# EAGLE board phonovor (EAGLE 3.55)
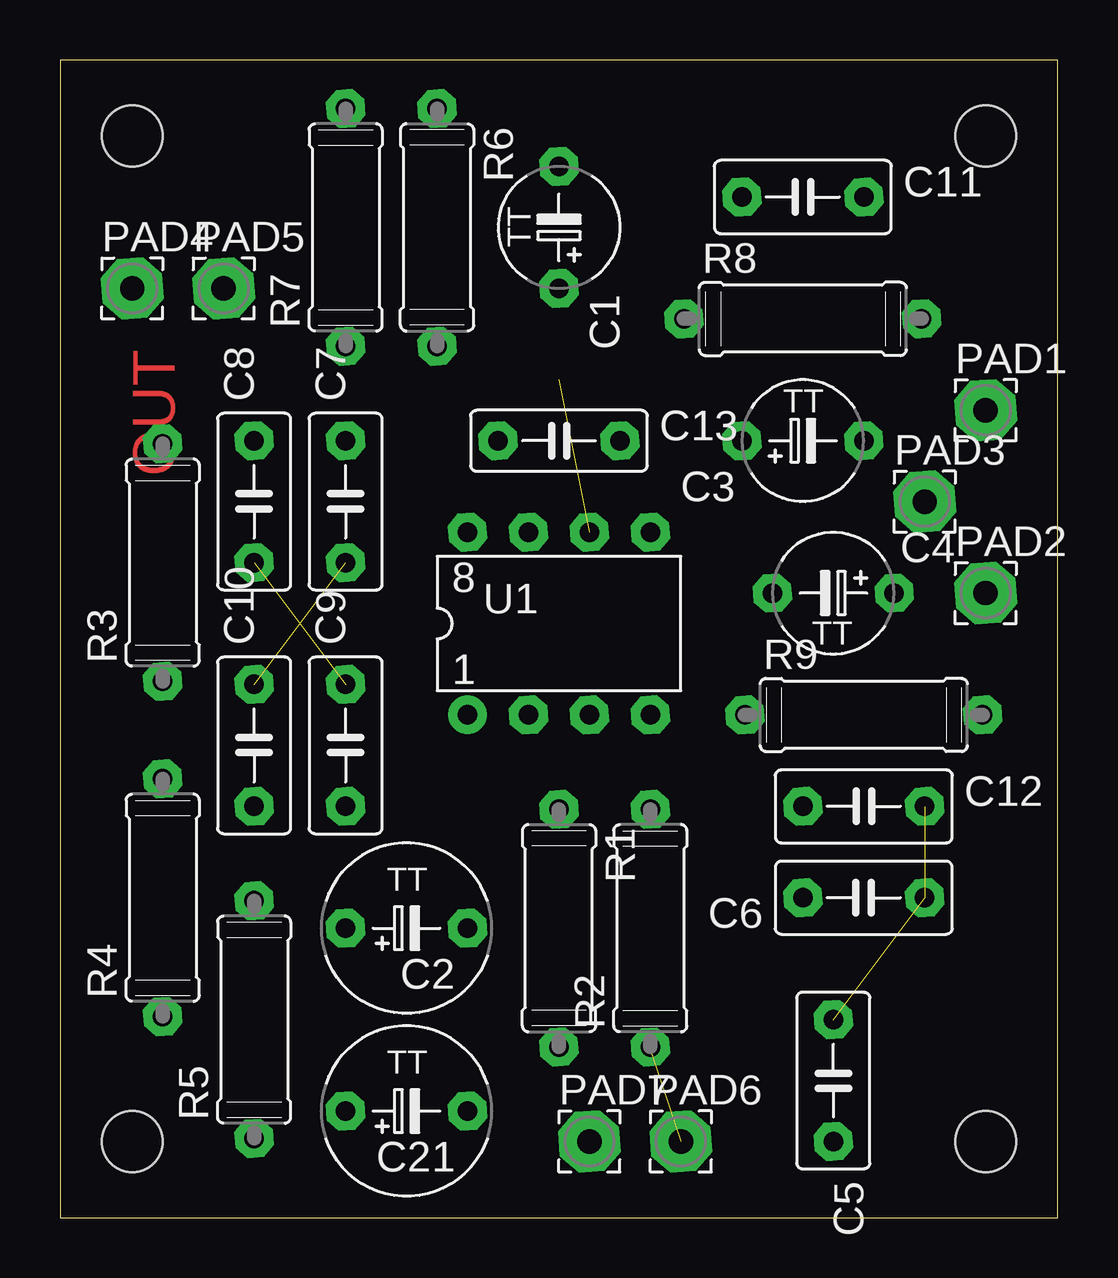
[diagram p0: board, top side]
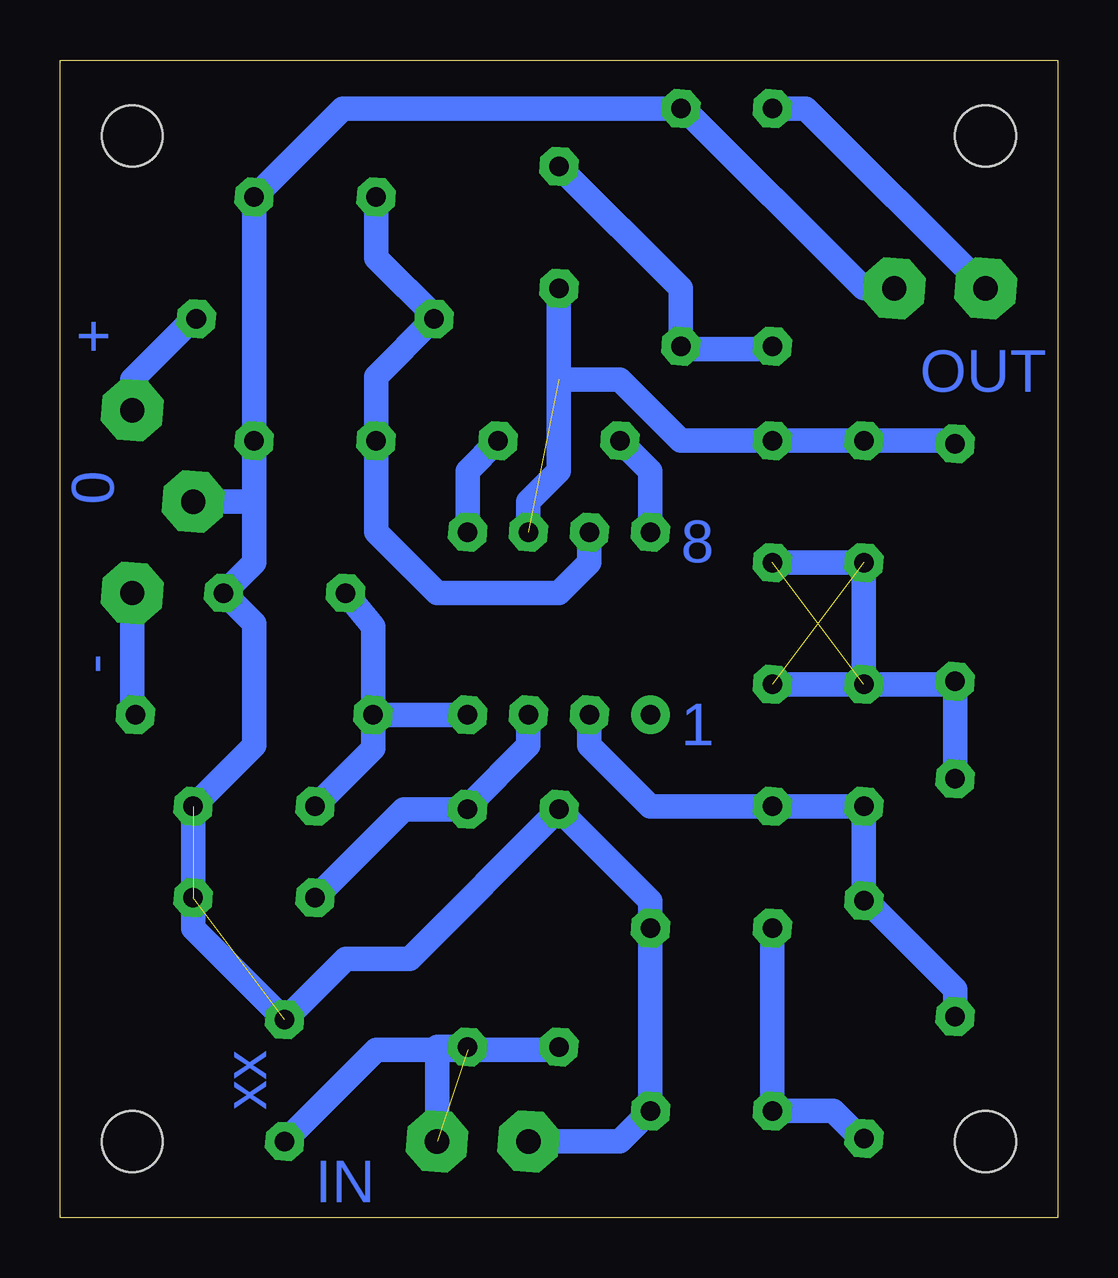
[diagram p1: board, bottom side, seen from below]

Size 41.58 x 48.25 mm. Coordinates in mm from the lower left corner, seen from the top.
Outline: 0,0 41.58,0 41.58,48.25 0,48.25 0,0
Copper layers used: Bottom
Holes 2.54 mm at 3.01,3.17 38.57,3.17 38.57,45.08 3.01,45.08

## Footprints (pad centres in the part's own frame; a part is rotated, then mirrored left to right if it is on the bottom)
P5-50 = drill 0.813 pad 1.6 octagon:  -2.54,0;  2.54,0
P5-70 = drill 0.813 pad 1.6 octagon:  -2.54,0;  2.54,0
B3 = drill 0.813 pad 1.6 octagon:  -2.54,0;  2.54,0
B2,5 = drill 0.813 pad 1.6 octagon:  -2.54,0;  2.54,0
54/1,0 = drill 1.016 pad 2.54 octagon:  0,0
09/10 = drill 0.813 pad 1.6 octagon:  -4.953,0;  4.953,0
L08 = drill 0.813 pad 1.6 round:  -3.81,-3.81 | drill 0.813 pad 1.6 octagon:  -1.27,-3.81;  1.27,-3.81;  3.81,-3.81;  3.81,3.81;  1.27,3.81;  -1.27,3.81;  -3.81,3.81

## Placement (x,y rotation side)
C1  47æ  [P5-50]  20.79,41.27 270 top
C2  220æ  [P5-70]  14.44,12.06 180 top
C3  47æ  [P5-50]  30.95,32.38 180 top
C4  47æ  [P5-50]  32.22,26.03 0 top
C5  ??p  [B3]  32.22,5.71 270 top
C6  10p  [B3]  33.49,13.33 180 top
C7  2.2n  [B3]  11.9,29.84 90 top
C8  5.6n  [B3]  8.09,29.84 90 top
C9  1n  [B3]  11.9,19.68 90 top
C10  22n  [B3]  8.09,19.68 90 top
C11  22p  [B3]  30.95,42.54 0 top
C12  22p  [B3]  33.49,17.14 0 top
C13  22p  [B2,5]  20.79,32.38 0 top
C21  220æ  [P5-70]  14.44,4.44 180 top
PAD1  +15V  [54/1,0]  38.57,33.65 0 top
PAD2  -15V  [54/1,0]  38.57,26.03 0 top
PAD3  0V  [54/1,0]  36.03,29.84 0 top
PAD4  OUT  [54/1,0]  3.01,38.73 0 top
PAD5  Masse  [54/1,0]  6.82,38.73 0 top
PAD6  IN  [54/1,0]  25.87,3.17 0 top
PAD7  Masse  [54/1,0]  22.06,3.17 0 top
R1  100kR  [09/10]  20.79,12.06 270 top
R2  1kR  [09/10]  24.6,12.06 90 top
R3  10kR  [09/10]  4.28,27.3 90 top
R4  120kR  [09/10]  4.28,13.33 90 top
R5  270R  [09/10]  8.09,8.25 90 top
R6  47kR  [09/10]  15.71,41.27 270 top
R7  100R  [09/10]  11.9,41.27 90 top
R8  220R  [09/10]  30.95,37.46 0 top
R9  220R  [09/10]  33.49,20.95 0 top
U1  NE5534A  [L08]  20.79,24.76 0 top

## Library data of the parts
C1-C4 C21 = cap-tant
C5-C13 = cap-wi
PAD1-PAD7 = wirepad
R1-R9 = r
U1 = linear

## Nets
0V: C2. C3. C4. C5. C6. C11. C12. C21. PAD3. PAD5. PAD7. R1. R6.
+15V: PAD1. R8.
-15V: PAD2. R9.
N$1: C6. R2. U1.
N$2: C5. PAD6. R1. R2.
N$3: PAD4. R7.
N$4: C4. C12. R9. U1.
N$5: C2. C21. R5.
N$7: C13. U1.
N$8: C13. U1.
N$9: C1. C7. C8. R3. U1.
N$10: C1. R6. R7.
N$13: C3. C11. R8. U1.
N$16: C9. C10. R4. R5. U1.
N$19: C7. C8. C9. C10. R3. R4.

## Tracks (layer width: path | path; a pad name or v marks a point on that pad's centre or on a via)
0V  (2 unrouted)
  Bottom 1.016: PAD5. 8.09,38.73 15.71,46.35 15.71,46.22 29.81,46.22 C11. 33.49,32.38 33.49,29.84 | PAD3. 33.49,29.84 | 33.49,29.84 33.49,27.3 C4. 33.49,24.76 33.49,19.68 C12. 36.03,13.33 36.03,12.06 32.22,8.25 29.68,10.79 27.01,10.79 20.79,17.01 16.98,13.2 16.98,12.06 16.98,4.44 18.25,3.17 PAD7.
+15V
  Bottom 1.016: R8. 36.03,37.46 38.57,34.92 PAD1.
-15V
  Bottom 1.016: R9. 38.57,20.95 PAD2.
N$1
  Bottom 1.016: 22.06,20.95 22.06,19.68 24.6,17.14 R2. 27.27,17.01 C6.
N$2  (1 unrouted)
  Bottom 1.016: C5. 28.41,6.98 24.6,6.98 | 24.6,6.98 24.6,7.11 25.87,7.11 PAD6. | R1. 20.92,6.98 24.6,6.98
N$3
  Bottom 1.016: R7. 10.5,46.22 PAD4.
N$4
  Bottom 1.016: 24.6,20.95 28.54,20.95 | 28.54,20.95 28.54,24.63 29.68,26.03 | 28.54,20.95 28.54,19.55 30.95,17.14
N$5
  Bottom 1.016: C2. C21. 9.36,4.44 8.09,3.17 8.09,3.3
N$7
  Bottom 1.016: C13. 24.6,31.11 24.6,28.57
N$8
  Bottom 1.016: 18.25,32.38 16.98,31.11 U1.
N$9  (1 unrouted)
  Bottom 1.016: R3. 4.41,32.38 C8. C7. 15.71,32.38 18.25,34.92 20.79,34.92 | 22.06,28.57 22.06,29.84 20.79,31.11 20.79,34.92 | 20.79,34.92 C1.
N$10
  Bottom 1.016: 11.9,36.32 12.03,36.19 15.71,36.19 R6. 15.71,38.73 20.79,43.81
N$13
  Bottom 1.016: 28.41,42.54 28.41,40 25.87,37.46 26,37.46 28.41,35.05 C3. 28.41,28.57 25.87,26.03 20.79,26.03 19.52,27.3 19.52,28.57
N$16
  Bottom 1.016: 4.28,8.38 4.28,9.52 8.09,13.33 R5. 8.09,17.14 11.9,17.14 16.98,17.14 19.52,19.68 19.52,20.95
N$19  (2 unrouted)
  Bottom 1.016: 11.9,27.3 8.09,27.3 C10. | C9. C10. | C10. 4.28,22.22 4.28,22.35 R4.

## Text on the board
Top: OUT
Bottom: + | OUT | 0 | 8 | - | 1 | xx | IN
